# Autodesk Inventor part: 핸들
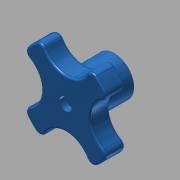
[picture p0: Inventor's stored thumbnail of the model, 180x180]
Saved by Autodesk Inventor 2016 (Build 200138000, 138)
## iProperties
Created: 2018-01
Part Number: 핸들
Material: ABS 플라스틱
Document SubType Name: Modeling
Designer: mduedu
Density: 1 g/cm^3
Appearance: 청록색
Author: mduedu
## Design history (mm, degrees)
sketch "스케치1"
  geometry: C1 r 10 at (0, 0); C2 r 25 at (0, 0); 1 further point
  constraints: 2 centre point, 2 coincident
  dimensions: "d0" = 20 diameter of C1; "d1" = 50 diameter of C2
extrude "돌출1" new body sketch "스케치1" distance "d2" = 15; taper "d3" = 0 deg
extrude "돌출2" join sketch "스케치1" distance "d4" = 10; taper "d5" = 0 deg
sketch "스케치2" dims "d8" = 15
  geometry: L1 (-6, -6)-(-4.5, -6); L2 (6, -6)-(6, -4.5); L3 (6, 6)-(4.5, 6); L4 (-6, 6)-(-6, 4.5); L5 (-6, -6)-(6, 6); L6 (6, -6)-(-6, 6); L7 (-4.5, 6)-(-6, 6); L8 (4.5, 6)-(-4.5, 6); L9 (6, 4.5)-(6, 6); L10 (6, -4.5)-(6, 4.5); L11 (4.5, -6)-(6, -6); L12 (-4.5, -6)-(4.5, -6); L13 (-6, -4.5)-(-6, -6); L14 (-6, 4.5)-(-6, -4.5); 2 further points
  constraints: 28 end point, 18 parallel, 9 perpendicular, 3 horizontal, 2 midpoint, 1 coincident, 10 other
  dimensions: "d6" = 12 distance of L4.start L3.start; "d7" = 12 distance of L3.start L2.start
extrude "돌출3" cut sketch "스케치2" distance "d9" = 15; taper "d10" = 0 deg
sketch "스케치3"
  geometry: C1 r 12.5 at (25, 0); 2 further points
  constraints: 2 horizontal alignment, 1 centre point, 1 other
  dimensions: "d14" = 25 diameter of C1
extrude "돌출4" cut sketch "스케치3" stored distance "d15" = 15; taper "d16" = 0 deg
fillet "모깎기1" dims "d20" = 3
fillet "모깎기2" dims "d24" = 1
sketch "스케치4"
  geometry: 2 further points
  constraints: 1 coincident
sketch "스케치5"
  geometry: 2 further points
  constraints: 1 coincident
hole "구멍1" sketch "스케치5" at (0, 0) diameter "d25" = 3.4; stored, may be unused: countersink angle "d29" = 90 deg, drill point angle "d31" = 0 deg; dims "d26" = 6, "d27" = 6.5, "d28" = 3.4, "d30" = 8
node "솔리드1"
pattern_circular "원형 패턴1" dims angle "d18" = 360 deg
pattern_circular "원형 패턴2" dims angle "d22" = 360 deg
node "투영된 루프1"
